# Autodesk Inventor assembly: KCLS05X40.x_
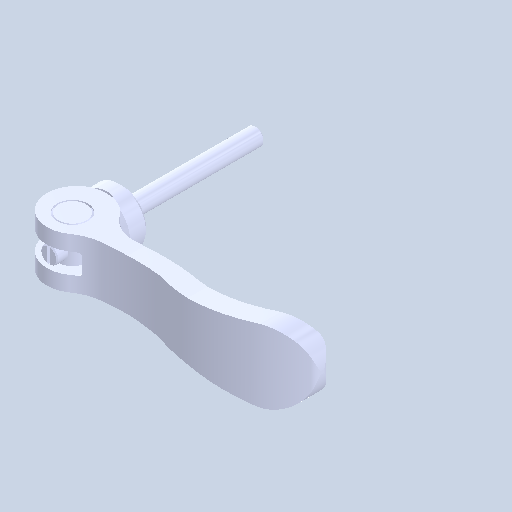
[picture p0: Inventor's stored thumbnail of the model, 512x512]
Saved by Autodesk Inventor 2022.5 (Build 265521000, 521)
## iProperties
Created: 2024-08
Part Number: KCLS05X40.x_
Document SubType Name: Assembly
Designer: ImaoCorp
Author: ImaoCorp
Sending System: SOLIDWORKS 2022-2022290
MC: AMD64
MC_MODEL: Intel64 Family 6 Model 60 Stepping 3, GenuineIntel
OS: Windows_NT
FRU: Parasolid Version 33.1, build 260,  4-25-2022
FORMAT: text
GUISE: transmit
KEY: FILEKCLS05X40.x_t
DATE: Thu Aug 29 10:54:43 2024
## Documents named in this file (5)
- Y:\5.更新分\2024年対応\1001_KCL\データ\kcls05x40\KCLS05X40.x_.iam
- Y:\5.更新分\2024年対応\1001_KCL\データ\kcls05x40\KCLS05X40_01.ipt
- Y:\5.更新分\2024年対応\1001_KCL\データ\kcls05x40\KCLS05X40_02.ipt
- Y:\5.更新分\2024年対応\1001_KCL\データ\kcls05x40\KCLS05X40_03.ipt
- Y:\5.更新分\2024年対応\1001_KCL\データ\kcls05x40\KCLS05X40_04.ipt
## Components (4 placed, 4 different names)
1. KCLS05X40_01
2. KCLS05X40_02
3. KCLS05X40_03
4. KCLS05X40_04
